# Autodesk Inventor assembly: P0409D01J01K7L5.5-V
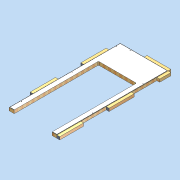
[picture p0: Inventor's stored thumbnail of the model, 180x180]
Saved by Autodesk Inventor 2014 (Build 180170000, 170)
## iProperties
Created: 2011-04
Part Number: P0409D01J01K7L5.5-V
Document SubType Name: Assembly
Designer: david.appleford
Description: 1w x 2w  01 Door Panel - 6 Locks 5.5 Lugs
Mass: 26000 g
Surface Area: 43154.8 cm^2
Volume: 111791 cm^3
Density: 0.232577 g/cm^3
Cost Center: £179.00
Justset: False
Title: 1w x 2.25w 01 Panel - 6 Locks 5.5 Lugs
Author: david.appleford
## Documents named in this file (5)
- C:\Documents and Settings\john.everitt\Local Settings\My Documents\Vault\Production MkII\VIRTUAL ELEMENTS\Virtual Walls\Virtual Timber + MgO\P0409D01J01K7L5.5-V.iam
- C:\Documents and Settings\john.everitt\Local Settings\My Documents\Vault\Production MkII\VIRTUAL ELEMENTS\Virtual Lugs\Superceded Lugs\LA02C3V.ipt
- C:\Documents and Settings\john.everitt\Local Settings\My Documents\Vault\Production MkII\VIRTUAL ELEMENTS\Virtual Lugs\Superceded Lugs\LA02M3V.ipt
- C:\Documents and Settings\john.everitt\Local Settings\My Documents\Vault\Production MkII\VIRTUAL ELEMENTS\Virtual Lugs\Superceded Lugs\LA01C3V.ipt
- C:\Documents and Settings\john.everitt\Local Settings\My Documents\Vault\Production MkII\Virtual Elements\Virtual Walls\Virtual Timber + MgO\P0409D01J01K7-V.ipt
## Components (7 placed, 4 different names)
1. P0409D01J01K7-V:1 — Mate:1, Flush:1, Flush:2, Mate:4, Flush:7, Flush:8, Mate:5, Mate:6, Flush:9, Flush:10, Mate:7, Flush:11, Mate:14, Flush:12, Flush:13
2. LA02C3V:1 — Mate:1, Flush:1, Flush:2, Mate:9, Mate:13
3. LA02C3V:3 — Mate:4, Flush:7, Flush:8
4. LA02M3V:5 — Mate:6, Flush:9, Mate:12
5. LA02M3V:2 — Mate:5, Flush:10, Mate:12, Mate:13
6. LA02M3V:4 — Mate:7, Flush:11, Mate:9
7. LA01C3V:1 — Mate:14, Flush:12, Flush:13
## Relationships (18: Mate 9, Flush 9)
- Mate:1: P0409D01J01K7-V:1 ↔ LA02C3V:1
- Flush:1: P0409D01J01K7-V:1 ↔ LA02C3V:1
- Flush:2: P0409D01J01K7-V:1 ↔ LA02C3V:1
- Mate:4: P0409D01J01K7-V:1 ↔ LA02C3V:3
- Flush:7: P0409D01J01K7-V:1 ↔ LA02C3V:3
- Flush:8: P0409D01J01K7-V:1 ↔ LA02C3V:3
- Mate:5: P0409D01J01K7-V:1 ↔ LA02M3V:2
- Mate:6: P0409D01J01K7-V:1 ↔ LA02M3V:5
- Flush:9: P0409D01J01K7-V:1 ↔ LA02M3V:5
- Flush:10: P0409D01J01K7-V:1 ↔ LA02M3V:2
- Mate:7: P0409D01J01K7-V:1 ↔ LA02M3V:4
- Flush:11: P0409D01J01K7-V:1 ↔ LA02M3V:4
- Mate:9: LA02C3V:1 ↔ LA02M3V:4
- Mate:12: LA02M3V:5 ↔ LA02M3V:2
- Mate:13: LA02C3V:1 ↔ LA02M3V:2
- Mate:14: P0409D01J01K7-V:1 ↔ LA01C3V:1
- Flush:12: P0409D01J01K7-V:1 ↔ LA01C3V:1
- Flush:13: P0409D01J01K7-V:1 ↔ LA01C3V:1
## Named parameters: t = 1 mm, Cl = 2 mm
